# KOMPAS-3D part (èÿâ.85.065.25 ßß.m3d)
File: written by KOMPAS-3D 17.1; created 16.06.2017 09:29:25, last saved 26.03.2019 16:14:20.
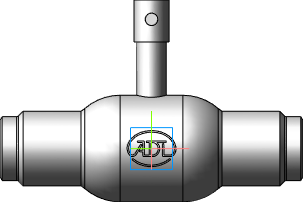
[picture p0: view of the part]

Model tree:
1. Операция без истории:2  (labels: Сталь 20  ГОСТ 1050-88)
